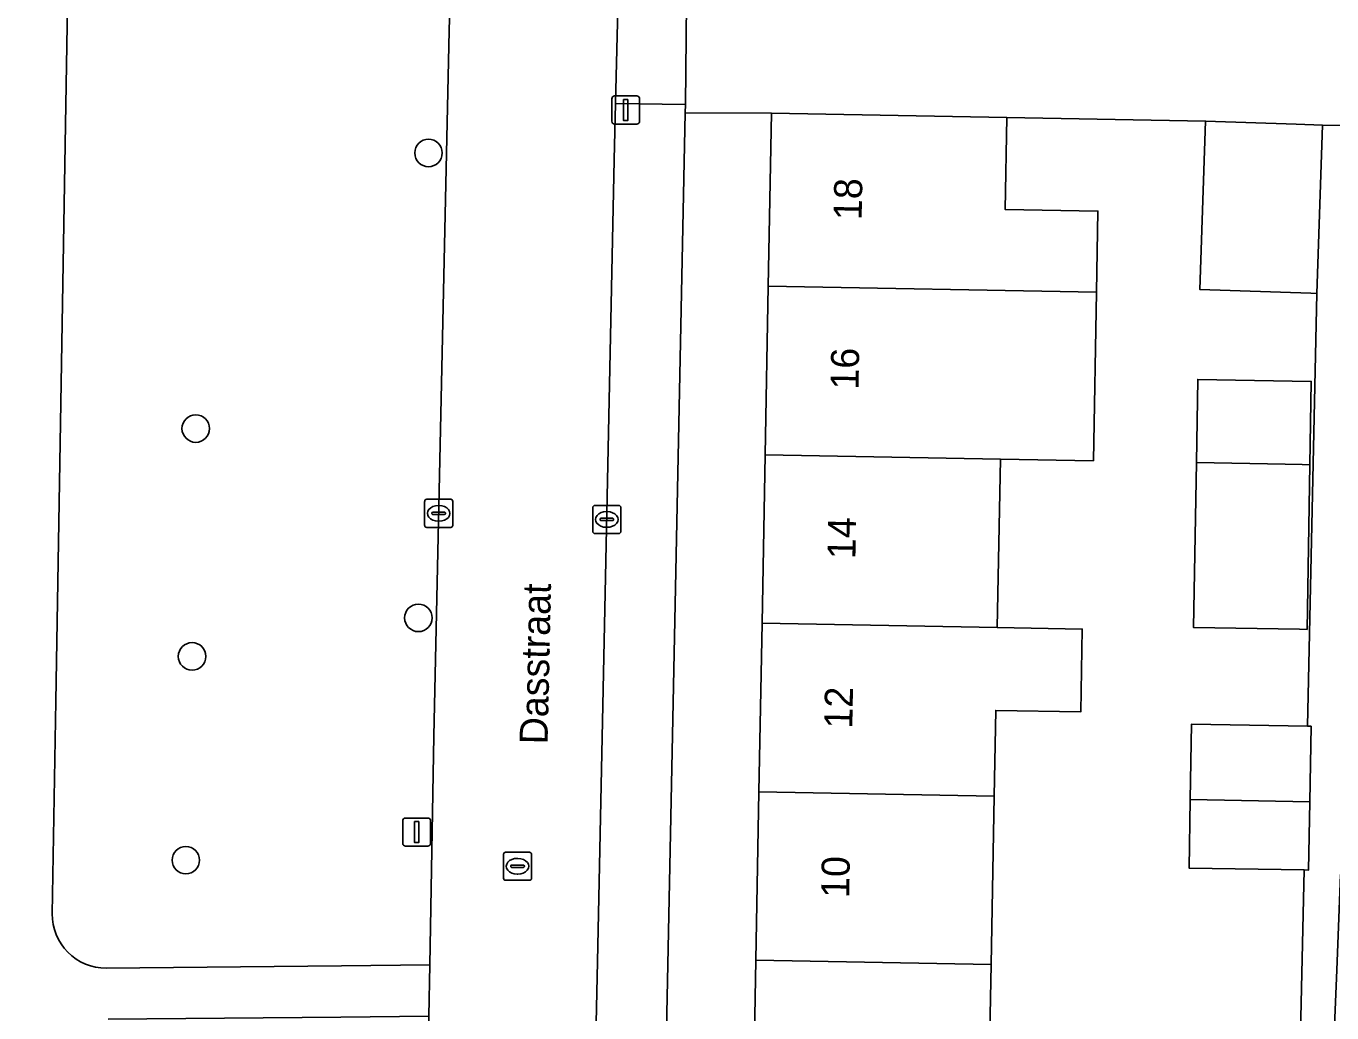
# Model space of a CAD drawing. Extents: x 160023 to 161302, y 384750 to 385707.
# Drawn here: x 160601.98 to 160648.47, y 385068.83 to 385103.94 of the extents above; entities that cross this region are included whole.
import ezdxf

# ---------------------------------------------------------------- set-up
doc = ezdxf.new("R2010")
doc.units = 0
for name, color, linetype in [('IMGEO_Boom', 7, 'Continuous'), ('IMGEO_Erf', 7, 'Continuous'), ('IMGEO_Groenvoorziening', 7, 'Continuous'), ('IMGEO_Kolk', 7, 'Continuous'), ('IMGEO_Lichtmast', 7, 'Continuous'), ('IMGEO_Muur', 7, 'Continuous'), ('IMGEO_Openbare_ruimte_label', 7, 'Continuous'), ('IMGEO_Pand', 7, 'Continuous'), ('IMGEO_Pand_nummerreeks', 7, 'Continuous'), ('IMGEO_Rijbaan_lokaal_open', 7, 'Continuous'), ('IMGEO_Rioolput', 7, 'Continuous'), ('IMGEO_Voetpad_halfverhard', 7, 'Continuous'), ('IMGEO_Voetpad_open', 7, 'Continuous')]:
    doc.layers.add(name, color=color, linetype=linetype)

msp = doc.modelspace()

# ---------------------------------------------------------------- linework, layer by layer
at = {"layer": 'IMGEO_Boom'}
for centre in [(160616.302, 385099.428), (160608.015, 385089.62), (160615.942, 385082.883), (160607.884, 385081.515), (160607.664, 385074.262)]:
    msp.add_circle(centre, 0.489, dxfattribs=at)
at = {"layer": 'IMGEO_Erf'}
for points in [[(160628.07, 385076.698), (160628.181, 385082.695), (160628.291, 385088.692), (160628.402, 385094.689), (160628.515, 385100.842), (160625.445, 385100.857), (160624.337, 385046.664), (160627.498, 385046.657), (160627.628, 385052.71), (160627.739, 385058.707), (160627.849, 385064.704), (160627.96, 385070.701)], [(160643.693, 385091.369), (160647.732, 385091.302), (160647.682, 385088.335), (160647.584, 385082.473), (160647.314, 385082.478), (160643.546, 385082.541), (160643.644, 385088.409)]]:
    msp.add_lwpolyline(points, close=True, dxfattribs=at)
msp.add_lwpolyline([(160647.327, 385067.068), (160647.48, 385073.914), (160643.382, 385073.983), (160643.422, 385076.416), (160643.468, 385079.1), (160647.595, 385079.031), (160647.939, 385094.427), (160647.714, 385094.434), (160643.768, 385094.566), (160643.969, 385100.561), (160636.89, 385100.688), (160636.83, 385097.419), (160640.14, 385097.359), (160640.087, 385094.474), (160639.976, 385088.477), (160636.666, 385088.538), (160636.556, 385082.541), (160639.583, 385082.486), (160639.528, 385079.537), (160636.501, 385079.593), (160636.445, 385076.544), (160636.335, 385070.547), (160636.224, 385064.55)], dxfattribs=at)
at = {"layer": 'IMGEO_Groenvoorziening'}
for points in [[(160617.044, 385103.79), (160617.43, 385117.621), (160614.133, 385117.699), (160605.686, 385117.9), (160605.504, 385107.037), (160603.489, 385107.085), (160603.449, 385104.674), (160603.035, 385079.917), (160602.909, 385072.356)], [(160604.827, 385070.424), (160613.21, 385070.504), (160616.352, 385070.534), (160616.494, 385078.673), (160617.044, 385103.79)]]:
    msp.add_lwpolyline(points, dxfattribs=at)
msp.add_arc((160604.809, 385072.324), 1.901, 179.05, 270.5333, dxfattribs=at)
at = {"layer": 'IMGEO_Kolk'}
for p, q in [((160616.166, 385086.177), (160616.166, 385087.029)), ((160616.241, 385087.103), (160617.093, 385087.103)), ((160616.654, 385086.883), (160616.679, 385086.883)), ((160617.167, 385087.029), (160617.167, 385086.177)), ((160622.226, 385086.887), (160623.078, 385086.887)), ((160616.425, 385086.597), (160616.425, 385086.609)), ((160616.863, 385086.56), (160616.465, 385086.56)), ((160616.468, 385086.646), (160616.866, 385086.646)), ((160616.909, 385086.609), (160616.909, 385086.597)), ((160622.151, 385085.961), (160622.151, 385086.813)), ((160622.453, 385086.43), (160622.851, 385086.43)), ((160622.639, 385086.667), (160622.664, 385086.667)), ((160623.152, 385086.813), (160623.152, 385085.961)), ((160617.093, 385086.103), (160616.241, 385086.103)), ((160616.677, 385086.323), (160616.652, 385086.323)), ((160622.41, 385086.381), (160622.41, 385086.393)), ((160622.848, 385086.344), (160622.45, 385086.344)), ((160622.662, 385086.107), (160622.637, 385086.107)), ((160622.894, 385086.393), (160622.894, 385086.381)), ((160623.078, 385085.887), (160622.226, 385085.887))]:
    msp.add_line(p, q, dxfattribs=at)
for points in [[(160616.166, 385086.177), (160616.166, 385087.029)], [(160616.241, 385087.103), (160617.093, 385087.103)], [(160617.167, 385087.029), (160617.167, 385086.177)], [(160622.226, 385086.887), (160623.078, 385086.887)], [(160622.151, 385085.961), (160622.151, 385086.813)], [(160623.152, 385086.813), (160623.152, 385085.961)], [(160617.093, 385086.103), (160616.241, 385086.103)], [(160623.078, 385085.887), (160622.226, 385085.887)]]:
    msp.add_lwpolyline(points, dxfattribs=at)
for centre, radius, start, end in [((160616.243, 385087.027), 0.0765, 91.552, 178.448), ((160616.243, 385087.027), 0.0765, 91.552, 178.448), ((160617.091, 385087.027), 0.0765, 1.552, 88.448), ((160617.091, 385087.027), 0.0765, 1.552, 88.448), ((160622.228, 385086.811), 0.0765, 91.552, 178.448), ((160622.228, 385086.811), 0.0765, 91.552, 178.448), ((160623.076, 385086.811), 0.0765, 1.552, 88.448), ((160623.076, 385086.811), 0.0765, 1.552, 88.448), ((160616.465, 385086.606), 0.0403, 85.8775, 175.7526), ((160616.462, 385086.596), 0.0366, 178.938, 274.7102), ((160616.866, 385086.603), 0.043, 264.8664, 352.4533), ((160616.87, 385086.608), 0.0386, 1.7309, 96.639), ((160622.45, 385086.39), 0.0403, 85.8775, 175.7526), ((160622.855, 385086.392), 0.0386, 1.7309, 96.639), ((160616.243, 385086.179), 0.0765, 181.552, 268.448), ((160616.243, 385086.179), 0.0765, 181.552, 268.448), ((160617.091, 385086.179), 0.0765, 271.552, 358.448), ((160617.091, 385086.179), 0.0765, 271.552, 358.448), ((160622.228, 385085.963), 0.0765, 181.552, 268.448), ((160622.228, 385085.963), 0.0765, 181.552, 268.448), ((160622.447, 385086.38), 0.0366, 178.938, 274.7102), ((160622.851, 385086.387), 0.043, 264.8664, 352.4533), ((160623.076, 385085.963), 0.0765, 271.552, 358.448), ((160623.076, 385085.963), 0.0765, 271.552, 358.448)]:
    msp.add_arc(centre, radius, start, end, dxfattribs=at)
for centre, major_axis, ratio, start_param, end_param in [((160616.653, 385086.603), (-0.387, 0.002), 0.722429, 4.712389, 7.853982), ((160616.678, 385086.603), (-0.39, 0.002), 0.717154, 1.570796, 4.712389), ((160622.638, 385086.387), (-0.387, 0.002), 0.722429, 4.712389, 7.853982), ((160622.663, 385086.387), (-0.39, 0.002), 0.717154, 1.570796, 4.712389)]:
    msp.add_ellipse(centre, major_axis=major_axis, ratio=ratio, start_param=start_param, end_param=end_param, dxfattribs=at)
at = {"layer": 'IMGEO_Lichtmast'}
for p, q in [((160622.83, 385100.556), (160622.83, 385101.356)), ((160622.83, 385101.356), (160622.83, 385100.556)), ((160622.93, 385101.456), (160623.72, 385101.456)), ((160623.72, 385101.456), (160622.93, 385101.456)), ((160623.82, 385101.356), (160623.82, 385100.556)), ((160623.82, 385100.556), (160623.82, 385101.356)), ((160623.72, 385100.456), (160622.93, 385100.456)), ((160622.93, 385100.456), (160623.72, 385100.456)), ((160615.487, 385075.761), (160616.277, 385075.761)), ((160616.277, 385075.761), (160615.487, 385075.761)), ((160615.387, 385074.861), (160615.387, 385075.661)), ((160615.387, 385075.661), (160615.387, 385074.861)), ((160616.377, 385075.661), (160616.377, 385074.861)), ((160616.377, 385074.861), (160616.377, 385075.661)), ((160616.277, 385074.761), (160615.487, 385074.761)), ((160615.487, 385074.761), (160616.277, 385074.761))]:
    msp.add_line(p, q, dxfattribs=at)
for points in [[(160623.25, 385101.331), (160623.4, 385101.331), (160623.4, 385100.581), (160623.25, 385100.581), (160623.25, 385101.331)], [(160615.807, 385075.636), (160615.957, 385075.636), (160615.957, 385074.886), (160615.807, 385074.886), (160615.807, 385075.636)]]:
    msp.add_lwpolyline(points, dxfattribs=at)
for centre, start, end in [((160622.93, 385101.356), 90, 180), ((160622.93, 385101.356), 90, 180), ((160623.72, 385101.356), 0, 90), ((160623.72, 385101.356), 360, 90), ((160622.93, 385100.556), 180, 270), ((160622.93, 385100.556), 180, 270), ((160623.72, 385100.556), 270, 0), ((160623.72, 385100.556), 270, 0), ((160615.487, 385075.661), 90, 180), ((160615.487, 385075.661), 90, 180), ((160616.277, 385075.661), 0, 90), ((160616.277, 385075.661), 360, 90), ((160615.487, 385074.861), 180, 270), ((160615.487, 385074.861), 180, 270), ((160616.277, 385074.861), 270, 0), ((160616.277, 385074.861), 270, 0)]:
    msp.add_arc(centre, 0.1, start, end, dxfattribs=at)
at = {"layer": 'IMGEO_Muur'}
msp.add_lwpolyline([(160636.89, 385100.688), (160643.969, 385100.561)], dxfattribs=at)
at = {"layer": 'IMGEO_Pand'}
for points in [[(160628.515, 385100.842), (160628.402, 385094.689), (160640.087, 385094.474), (160640.14, 385097.359), (160636.83, 385097.419), (160636.89, 385100.688)], [(160648.14, 385100.422), (160647.203, 385100.453), (160643.969, 385100.561), (160643.768, 385094.566), (160647.714, 385094.434), (160647.939, 385094.427)], [(160628.402, 385094.689), (160628.291, 385088.692), (160636.666, 385088.538), (160639.976, 385088.477), (160640.087, 385094.474)], [(160647.732, 385091.302), (160643.693, 385091.369), (160643.644, 385088.409), (160646.806, 385088.351), (160647.412, 385088.34), (160647.682, 385088.335)], [(160636.556, 385082.541), (160636.666, 385088.538), (160628.291, 385088.692), (160628.181, 385082.695)], [(160647.682, 385088.335), (160647.412, 385088.34), (160646.806, 385088.351), (160643.644, 385088.409), (160643.546, 385082.541), (160647.314, 385082.478), (160647.584, 385082.473)], [(160628.181, 385082.695), (160628.07, 385076.698), (160636.445, 385076.544), (160636.501, 385079.593), (160639.528, 385079.537), (160639.583, 385082.486), (160636.556, 385082.541)], [(160647.595, 385079.031), (160643.468, 385079.1), (160643.422, 385076.416), (160647.683, 385076.337), (160647.728, 385079.029)], [(160636.335, 385070.547), (160636.445, 385076.544), (160628.07, 385076.698), (160627.96, 385070.701)], [(160647.683, 385076.337), (160643.422, 385076.416), (160643.382, 385073.983), (160647.48, 385073.914), (160647.642, 385073.911)], [(160636.224, 385064.55), (160636.335, 385070.547), (160627.96, 385070.701), (160627.849, 385064.704)]]:
    msp.add_lwpolyline(points, close=True, dxfattribs=at)
at = {"layer": 'IMGEO_Rijbaan_lokaal_open'}
for points in [[(160622.916, 385099.184), (160622.965, 385101.188), (160623.082, 385106.004), (160623.722, 385132.207), (160617.844, 385132.455), (160617.723, 385128.133), (160617.484, 385119.568), (160617.43, 385117.621), (160617.044, 385103.79), (160616.494, 385078.673), (160616.352, 385070.534), (160616.32, 385068.707), (160615.997, 385050.184), (160615.918, 385045.67), (160621.727, 385043.212), (160621.803, 385046.719), (160622.325, 385070.649)], [(160672.024, 385105.162), (160669.136, 385105.156), (160661.759, 385105.29), (160657.76, 385105.344), (160652.724, 385105.411), (160649.545, 385105.482), (160648.001, 385105.514), (160643.958, 385105.551), (160637.008, 385105.684), (160628.685, 385105.853), (160625.507, 385105.974), (160625.449, 385101.157), (160625.445, 385100.857), (160628.515, 385100.842), (160636.89, 385100.688), (160643.969, 385100.561), (160647.203, 385100.453), (160648.14, 385100.422), (160649.595, 385100.412), (160657.747, 385100.327), (160661.746, 385100.285), (160669.124, 385100.133), (160671.933, 385100.035)]]:
    msp.add_lwpolyline(points, close=True, dxfattribs=at)
at = {"layer": 'IMGEO_Rioolput'}
for p, q in [((160618.973, 385073.62), (160618.973, 385074.472)), ((160619.048, 385074.546), (160619.9, 385074.546)), ((160619.461, 385074.326), (160619.486, 385074.326)), ((160619.974, 385074.472), (160619.974, 385073.62)), ((160619.232, 385074.04), (160619.232, 385074.052)), ((160619.67, 385074.003), (160619.272, 385074.003)), ((160619.275, 385074.089), (160619.673, 385074.089)), ((160619.716, 385074.052), (160619.716, 385074.04)), ((160619.9, 385073.546), (160619.048, 385073.546)), ((160619.484, 385073.766), (160619.459, 385073.766))]:
    msp.add_line(p, q, dxfattribs=at)
for points in [[(160618.973, 385073.62), (160618.973, 385074.472)], [(160619.048, 385074.546), (160619.9, 385074.546)], [(160619.974, 385074.472), (160619.974, 385073.62)], [(160619.9, 385073.546), (160619.048, 385073.546)]]:
    msp.add_lwpolyline(points, dxfattribs=at)
for centre, radius, start, end in [((160619.05, 385074.47), 0.0765, 91.552, 178.448), ((160619.05, 385074.47), 0.0765, 91.552, 178.448), ((160619.898, 385074.47), 0.0765, 1.552, 88.448), ((160619.898, 385074.47), 0.0765, 1.552, 88.448), ((160619.272, 385074.049), 0.0403, 85.8775, 175.7526), ((160619.269, 385074.039), 0.0366, 178.938, 274.7102), ((160619.673, 385074.046), 0.043, 264.8664, 352.4533), ((160619.677, 385074.051), 0.0386, 1.7309, 96.639), ((160619.05, 385073.622), 0.0765, 181.552, 268.448), ((160619.05, 385073.622), 0.0765, 181.552, 268.448), ((160619.898, 385073.622), 0.0765, 271.552, 358.448), ((160619.898, 385073.622), 0.0765, 271.552, 358.448)]:
    msp.add_arc(centre, radius, start, end, dxfattribs=at)
for centre, major_axis, ratio, start_param, end_param in [((160619.46, 385074.046), (-0.387, 0.002), 0.722429, 4.712389, 7.853982), ((160619.485, 385074.046), (-0.39, 0.002), 0.717154, 1.570796, 4.712389)]:
    msp.add_ellipse(centre, major_axis=major_axis, ratio=ratio, start_param=start_param, end_param=end_param, dxfattribs=at)
at = {"layer": 'IMGEO_Voetpad_halfverhard'}
for points in [[(160602.909, 385072.356), (160603.035, 385079.917), (160603.449, 385104.674), (160603.489, 385107.085), (160605.504, 385107.037), (160605.686, 385117.9), (160614.133, 385117.699), (160617.43, 385117.621), (160617.484, 385119.568), (160614.175, 385119.646), (160605.718, 385119.846), (160605.883, 385129.682), (160597.472, 385131.741), (160595.529, 385132.217), (160596.884, 385137.647), (160594.614, 385138.311), (160592.785, 385130.842), (160578.425, 385134.358), (160575.157, 385135.158), (160574.748, 385133.329), (160578.019, 385132.528), (160579.038, 385132.279), (160571.746, 385099.761)], [(160604.892, 385068.6), (160613.186, 385068.678), (160616.32, 385068.707), (160616.352, 385070.534), (160613.21, 385070.504), (160604.827, 385070.424)]]:
    msp.add_lwpolyline(points, dxfattribs=at)
msp.add_arc((160604.809, 385072.324), 1.901, 179.05, 270.5333, dxfattribs=at)
at = {"layer": 'IMGEO_Voetpad_open'}
for points in [[(160625.449, 385101.157), (160625.507, 385105.974), (160623.082, 385106.004), (160622.965, 385101.188)], [(160625.445, 385100.857), (160625.449, 385101.157), (160622.965, 385101.188), (160622.916, 385099.184), (160622.325, 385070.649), (160621.803, 385046.719), (160624.337, 385046.664)]]:
    msp.add_lwpolyline(points, close=True, dxfattribs=at)
msp.add_lwpolyline([(160648.52, 385067.231), (160648.64, 385070.344), (160648.772, 385073.752), (160648.934, 385073.746), (160649.028, 385079.094), (160648.912, 385079.098), (160648.963, 385082.487), (160649.009, 385085.536), (160649.049, 385088.162), (160649.186, 385088.159), (160649.238, 385091.16), (160649.365, 385094.438), (160649.482, 385097.477), (160649.595, 385100.412), (160648.14, 385100.422), (160647.939, 385094.427), (160647.595, 385079.031), (160647.728, 385079.029), (160647.683, 385076.337), (160647.642, 385073.911), (160647.48, 385073.914), (160647.327, 385067.068)], dxfattribs=at)

# ---------------------------------------------------------------- texts
at = {"layer": 'IMGEO_Openbare_ruimte_label'}
msp.add_text('Dasstraat', height=1, rotation=88.797, dxfattribs=at).set_placement((160620.544, 385078.377))
at = {"layer": 'IMGEO_Pand_nummerreeks'}
for s, p in [('18', (160631.725, 385097.034)), ('16', (160631.614, 385091.001)), ('14', (160631.503, 385084.97)), ('12', (160631.392, 385078.936)), ('10', (160631.281, 385072.912))]:
    msp.add_text(s, height=1, rotation=88.9445, dxfattribs=at).set_placement(p)

doc.saveas('drawing.dxf')
